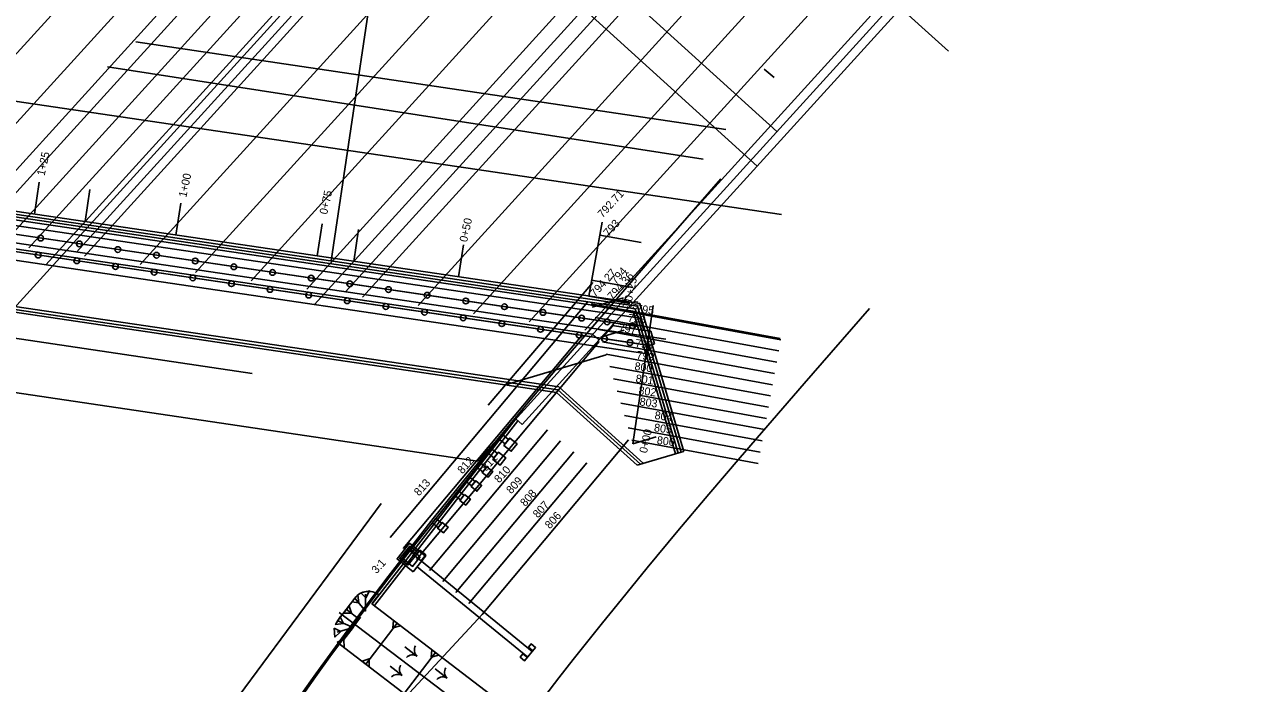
# Model space of a CAD drawing. Extents: x 1465887 to 1476191, y 569684 to 581027.
# Drawn here: x 1469836.1 to 1470052.7, y 573950.9 to 574066.2 of the extents above; entities that cross this region are included whole.
import ezdxf

# ---------------------------------------------------------------- set-up
doc = ezdxf.new("R2010")
doc.units = 0
for name, color, linetype in [('BR_P_Beam_Centerline', 7, 'Continuous'), ('BR_P_Brg_Centerline', 7, 'Continuous'), ('BR_P_Gen_Approach_Slab', 7, 'Continuous'), ('BR_P_Gen_Ground_Slope', 7, 'Continuous'), ('BR_P_Gen_Perforated_Pipe', 7, 'Continuous'), ('BR_P_Gen_Phase_Construction', 7, 'Continuous'), ('BR_P_Gen_Porous_Backfill', 7, 'Continuous'), ('BR_P_Gen_Profile_Grade', 7, 'Continuous'), ('BR_P_Gen_Slope_Protection', 7, 'Continuous'), ('BR_P_Rail_Object', 7, 'Continuous'), ('BR_P_Sub_Deep_Centerline', 7, 'Continuous'), ('BR_P_Sub_Deep_Hidden', 7, 'Continuous'), ('BR_P_Sub_Foot_Hidden', 7, 'Continuous'), ('BR_P_Sub_Hidden', 7, 'Continuous'), ('BR_P_Sub_Object', 7, 'Continuous'), ('BR_X_Sub_Hidden', 7, 'Continuous'), ('Default', 7, 'Continuous'), ('DR_P_Cells', 7, 'Continuous'), ('DR_P_Ditch', 7, 'Continuous'), ('DR_P_Erosion_Control', 7, 'Continuous'), ('DR_P_Headwall', 7, 'Continuous'), ('DR_P_Paved_Gutter', 7, 'Continuous'), ('DR_P_Storm_Sewer', 7, 'Continuous'), ('GK_Drainage_Nodes', 7, 'Continuous'), ('PV_X_Driveway', 7, 'Continuous'), ('PV_X_EOP', 7, 'Continuous'), ('PV_X_Shoulder', 7, 'Continuous'), ('RD_P_Anchor_Assembly', 7, 'Continuous'), ('SC_Scratch1', 7, 'Continuous'), ('SC_Scratch2', 7, 'Continuous')]:
    doc.layers.add(name, color=color, linetype=linetype)

msp = doc.modelspace()

# ---------------------------------------------------------------- linework, layer by layer
at = {"layer": 'BR_P_Beam_Centerline'}
for p, q in [((1469807.6, 574031.47), (1469918.67, 574153.77)), ((1469817.33, 574030.03), (1469928.4, 574152.33)), ((1469827.05, 574028.59), (1469938.12, 574150.89)), ((1469836.78, 574027.15), (1469947.84, 574149.45)), ((1469846.5, 574025.71), (1469957.57, 574148.01)), ((1469856.23, 574024.27), (1469967.29, 574146.57)), ((1469865.95, 574022.83), (1469977.02, 574145.13)), ((1469875.67, 574021.39), (1469986.74, 574143.69)), ((1469885.4, 574019.95), (1469996.47, 574142.25)), ((1469895.12, 574018.51), (1470006.19, 574140.81)), ((1469904.85, 574017.07), (1470015.91, 574139.37)), ((1469914.57, 574015.63), (1470025.64, 574137.93)), ((1469924.3, 574014.19), (1470035.36, 574136.49)), ((1469934.02, 574012.75), (1470045.09, 574135.05))]:
    msp.add_line(p, q, dxfattribs=at)
at = {"layer": 'BR_P_Brg_Centerline'}
msp.add_line((1469783.43, 574035.55), (1469948.19, 574011.16), dxfattribs=at)
at = {"layer": 'BR_P_Gen_Approach_Slab'}
for p, q in [((1469796.09, 574032.67), (1469935.4, 574012.04)), ((1469775.92, 574010.46), (1469915.23, 573989.83))]:
    msp.add_line(p, q, dxfattribs=at)
at = {"layer": 'BR_P_Gen_Ground_Slope'}
for p, q in [((1469934.72, 574018.72), (1469937.09, 574031.68)), ((1469936.67, 574029.4), (1469943.88, 574028.08)), ((1469935.23, 574021.53), (1469942.44, 574020.21)), ((1469934.72, 574018.72), (1469941.92, 574017.4)), ((1469934.51, 574017.67), (1469899.97, 573976.47)), ((1469935.13, 574017.34), (1469968.2, 574011.28)), ((1469935.18, 574017.15), (1469968.33, 574011.07)), ((1469935.82, 574014.99), (1469967.97, 574009.11)), ((1469936.46, 574012.84), (1469967.61, 574007.14)), ((1469933.52, 574011.82), (1469902.27, 573974.55)), ((1469936.56, 574010.77), (1469904.57, 573972.62)), ((1469937.1, 574010.69), (1469967.24, 574005.17)), ((1469937.75, 574008.54), (1469966.88, 574003.2)), ((1469938.39, 574006.39), (1469966.52, 574001.24)), ((1469939.03, 574004.24), (1469966.16, 573999.27)), ((1469939.67, 574002.09), (1469965.8, 573997.3)), ((1469940.31, 573999.94), (1469965.44, 573995.34)), ((1469940.95, 573997.79), (1469965.08, 573993.37)), ((1469927.49, 573995.29), (1469906.87, 573970.69)), ((1469941.59, 573995.64), (1469964.72, 573991.4)), ((1469929.79, 573993.36), (1469909.17, 573968.76)), ((1469941.69, 573993.54), (1469916.06, 573962.98)), ((1469942.23, 573993.49), (1469964.36, 573989.43)), ((1469932.09, 573991.43), (1469911.47, 573966.84)), ((1469934.39, 573989.5), (1469913.77, 573964.91)), ((1469916.06, 573962.98), (1469878.07, 573922.03))]:
    msp.add_line(p, q, dxfattribs=at)
at = {"layer": 'BR_P_Gen_Perforated_Pipe'}
for p, q in [((1469899.72, 574150.51), (1469997.64, 574061.59)), ((1469798.49, 574037.87), (1469942.86, 574016.5)), ((1469798.55, 574037.36), (1469942.47, 574016.05)), ((1469785.31, 574024.15), (1469929.51, 574002.81)), ((1469785.35, 574023.64), (1469929.29, 574002.33)), ((1469942.86, 574016.5), (1469950.38, 573991.23)), ((1469942.47, 574016.05), (1469949.9, 573991.09)), ((1469929.29, 574002.33), (1469943.76, 573989.26)), ((1469929.51, 574002.81), (1469944.32, 573989.43))]:
    msp.add_line(p, q, dxfattribs=at)
at = {"layer": 'BR_P_Gen_Phase_Construction'}
for p, q in [((1469839.72, 574024.19), (1469954.83, 574150.94)), ((1469845.12, 574026.42), (1469955.38, 574147.83)), ((1469886.75, 574017.22), (1470001.86, 574143.98)), ((1469892.16, 574019.46), (1469999.98, 574138.19))]:
    msp.add_line(p, q, dxfattribs=at)
at = {"layer": 'BR_P_Gen_Porous_Backfill'}
for p, q in [((1469785.4, 574023.13), (1469929.06, 574001.86)), ((1469929.06, 574001.86), (1469943.2, 573989.09)), ((1469943.2, 573989.09), (1469950.86, 573991.37))]:
    msp.add_line(p, q, dxfattribs=at)
at = {"layer": 'BR_P_Gen_Profile_Grade'}
msp.add_line((1465892.5, 569689.56), (1476184.47, 581022.69), dxfattribs=at)
at = {"layer": 'BR_P_Gen_Slope_Protection'}
for p, q in [((1469798.37, 574038.9), (1469943.64, 574017.39)), ((1469798.43, 574038.39), (1469942.04, 574017.13)), ((1469942.04, 574017.13), (1469943.25, 574016.95)), ((1469943.25, 574016.95), (1469950.86, 573991.37)), ((1469943.64, 574017.39), (1469951.34, 573991.52)), ((1469951.34, 573991.52), (1469950.86, 573991.37))]:
    msp.add_line(p, q, dxfattribs=at)
at = {"layer": 'BR_P_Rail_Object'}
for p, q in [((1469915.23, 573989.83), (1470067.44, 574157.44)), ((1469923.07, 573996.23), (1470068.55, 574156.43)), ((1469935.4, 574012.04), (1469936.51, 574011.03)), ((1469921.96, 573997.24), (1469923.07, 573996.23))]:
    msp.add_line(p, q, dxfattribs=at)
at = {"layer": 'BR_P_Sub_Deep_Centerline'}
for p, q in [((1469794.19, 574035.48), (1469943.45, 574013.38)), ((1469789.4, 574033.15), (1469943.18, 574010.39))]:
    msp.add_line(p, q, dxfattribs=at)
at = {"layer": 'BR_P_Sub_Deep_Hidden'}
for centre in [(1469838.84, 574028.87), (1469845.6, 574027.86), (1469852.36, 574026.86), (1469838.4, 574025.9), (1469845.16, 574024.9), (1469859.12, 574025.86), (1469865.88, 574024.86), (1469851.92, 574023.9), (1469858.68, 574022.9), (1469872.64, 574023.86), (1469879.4, 574022.86), (1469865.44, 574021.9), (1469872.2, 574020.89), (1469886.16, 574021.86), (1469892.92, 574020.86), (1469878.96, 574019.89), (1469885.72, 574018.89), (1469899.68, 574019.86), (1469906.44, 574018.86), (1469892.48, 574017.89), (1469899.24, 574016.89), (1469913.2, 574017.86), (1469919.96, 574016.86), (1469906, 574015.89), (1469912.76, 574014.89), (1469919.52, 574013.89), (1469926.72, 574015.86), (1469933.48, 574014.86), (1469937.93, 574014.2), (1469926.28, 574012.89), (1469933.04, 574011.89), (1469942.38, 574013.54), (1469937.49, 574011.23), (1469941.94, 574010.57)]:
    msp.add_circle(centre, 0.5, dxfattribs=at)
at = {"layer": 'BR_P_Sub_Foot_Hidden'}
for p, q in [((1469795.04, 574036.87), (1469943.7, 574014.86)), ((1469786.45, 574032.07), (1469944.6, 574008.66)), ((1469943.7, 574014.86), (1469944.33, 574012.74)), ((1469945.11, 574010.1), (1469945.3, 574009.47)), ((1469945.3, 574009.47), (1469944.6, 574008.66))]:
    msp.add_line(p, q, dxfattribs=at)
at = {"layer": 'BR_P_Sub_Hidden'}
for p, q in [((1469796.32, 574035.16), (1469939.21, 574014.01)), ((1469793.9, 574032.49), (1469936.78, 574011.33)), ((1469938.81, 574013.56), (1469939.21, 574014.01))]:
    msp.add_line(p, q, dxfattribs=at)
at = {"layer": 'BR_P_Sub_Object'}
for p, q in [((1469936.78, 574011.33), (1469938.81, 574013.56)), ((1469936.98, 574011.3), (1469939.01, 574013.53)), ((1469938.81, 574013.56), (1469944.51, 574012.72)), ((1469944.51, 574012.72), (1469945.6, 574012.56)), ((1469945.6, 574012.56), (1469946.25, 574010.36)), ((1469936.78, 574011.33), (1469945.3, 574010.07)), ((1469945.3, 574010.07), (1469946.25, 574010.36))]:
    msp.add_line(p, q, dxfattribs=at)
msp.add_lwpolyline([(1469936.78, 574011.33), (1469936.98, 574011.3), (1469939.01, 574013.53), (1469938.81, 574013.56)], close=True, dxfattribs=at)
at = {"layer": 'BR_X_Sub_Hidden'}
msp.add_line((1469968.46, 574033.03), (1469823.18, 574054.48), dxfattribs=at)
at = {"layer": 'Default'}
msp.add_lwpolyline([(1469867.09, 573922.18), (1469867.81, 573923.36), (1469870.08, 573927.01), (1469872.39, 573930.64), (1469874.73, 573934.25), (1469877.1, 573937.84), (1469879.51, 573941.42), (1469881.94, 573944.97), (1469884.41, 573948.51), (1469886.91, 573952.03), (1469889.43, 573955.53), (1469891.98, 573959.02), (1469894.55, 573962.49), (1469897.15, 573965.94), (1469899.77, 573969.38), (1469902.42, 573972.81), (1469903.75, 573974.52)], dxfattribs=at)
at = {"layer": 'DR_P_Cells'}
for points in [[(1469904, 573970.46), (1469906.19, 573973.19), (1469903.39, 573975.43), (1469901.2, 573972.7)], [(1469903.1, 573971.61), (1469904.88, 573973.82), (1469903.45, 573974.96), (1469901.67, 573972.75)], [(1469905.25, 573973.09), (1469903.9, 573971.4), (1469902.14, 573972.81), (1469903.5, 573974.49)]]:
    msp.add_lwpolyline(points, close=True, dxfattribs=at)
at = {"layer": 'DR_P_Ditch'}
msp.add_line((1469915.36, 573944.87), (1469891.08, 573963.33), dxfattribs=at)
at = {"layer": 'DR_P_Erosion_Control'}
for p, q in [((1469893.8, 573965.84), (1469890.76, 573961.87)), ((1469898.01, 573966.4), (1469896.8, 573964.82)), ((1469918.57, 573948.14), (1469896.8, 573964.82)), ((1469892.32, 573963.84), (1469894.64, 573962.08)), ((1469893.51, 573960.67), (1469891.89, 573958.58)), ((1469895.7, 573954.3), (1469901.18, 573961.45)), ((1469912.88, 573941.14), (1469891.32, 573957.67)), ((1469902.41, 573949.15), (1469907.89, 573956.3)), ((1469902.57, 573957.3), (1469904.67, 573955.69)), ((1469899.96, 573953.9), (1469902.06, 573952.28)), ((1469907.85, 573953.45), (1469909.95, 573951.84))]:
    msp.add_line(p, q, dxfattribs=at)
for points in [[(1469894.84, 573966.78), (1469896.37, 573967.09), (1469895.74, 573965.86)], [(1469893.25, 573965.21), (1469894.3, 573966.36), (1469894.52, 573965)], [(1469891.25, 573962.55), (1469890.44, 573961.21), (1469891.81, 573961.39)], [(1469892.79, 573964.41), (1469891.82, 573963.18), (1469893.2, 573963.19)], [(1469890.2, 573960.58), (1469890.32, 573959.02), (1469891.33, 573959.97)], [(1469900.57, 573961.94), (1469901.79, 573960.97), (1469900.45, 573960.66)], [(1469900.57, 573961.94), (1469901.79, 573960.97), (1469900.45, 573960.66)], [(1469890.69, 573958.13), (1469891.94, 573957.2), (1469891.89, 573958.58)], [(1469907.28, 573956.79), (1469908.51, 573955.82), (1469907.16, 573955.51)], [(1469907.28, 573956.79), (1469908.51, 573955.82), (1469907.16, 573955.51)], [(1469895.07, 573954.77), (1469896.33, 573953.83), (1469896.28, 573955.22)]]:
    msp.add_lwpolyline(points, close=True, dxfattribs=at)
for points in [[(1469893.79, 573965.84), (1469895.68, 573963.57), (1469895.67, 573966.51)], [(1469890.8, 573961.85), (1469893.51, 573960.67), (1469890.69, 573959.86)]]:
    msp.add_lwpolyline(points, dxfattribs=at)
for centre, radius, start, end in [((1469896.18, 573964.02), 3, 52.5361, 142.5361), ((1469903.91, 573954.39), 1.51, 59.558, 134.8196), ((1469905.73, 573956.76), 1.51, 150.2525, 225.5141), ((1469903.12, 573953.36), 1.51, 150.2525, 225.5141), ((1469911.01, 573952.91), 1.51, 150.2525, 225.5141), ((1469901.3, 573950.98), 1.51, 59.558, 134.8196), ((1469909.19, 573950.54), 1.51, 59.558, 134.8196)]:
    msp.add_arc(centre, radius, start, end, dxfattribs=at)
at = {"layer": 'DR_P_Headwall'}
msp.add_lwpolyline([(1469924.93, 573956.6), (1469924.16, 573957.23), (1469924.63, 573957.81), (1469925.41, 573957.18), (1469923.51, 573954.86), (1469922.73, 573955.49), (1469923.21, 573956.07), (1469923.98, 573955.44)], dxfattribs=at)
at = {"layer": 'DR_P_Paved_Gutter'}
for p, q in [((1469896.83, 573964.85), (1469921.96, 573997.24)), ((1469897.22, 573964.54), (1469922.33, 573996.9)), ((1469903.8, 573973.38), (1469904.2, 573973.08))]:
    msp.add_line(p, q, dxfattribs=at)
at = {"layer": 'DR_P_Storm_Sewer'}
for p, q in [((1469924.06, 573955.52), (1469904.7, 573971.34)), ((1469924.85, 573956.49), (1469905.49, 573972.31))]:
    msp.add_line(p, q, dxfattribs=at)
at = {"layer": 'GK_Drainage_Nodes'}
for p, q in [((1469902.3, 573974.07), (1469902.3, 573974.07)), ((1469902.82, 573973.65), (1469902.82, 573973.65)), ((1469904.37, 573973.79), (1469904.37, 573973.79)), ((1469903.02, 573972.1), (1469903.02, 573972.1)), ((1469903.7, 573972.95), (1469903.7, 573972.95)), ((1469903.7, 573972.95), (1469903.7, 573972.95)), ((1469903.7, 573972.95), (1469903.7, 573972.95)), ((1469903.99, 573972.71), (1469903.99, 573972.71)), ((1469903.99, 573972.71), (1469903.99, 573972.71)), ((1469904.57, 573972.24), (1469904.57, 573972.24)), ((1469905.09, 573971.82), (1469905.09, 573971.82)), ((1469923.68, 573956.65), (1469923.68, 573956.65)), ((1469924.46, 573956.02), (1469924.46, 573956.02)), ((1469924.46, 573956.02), (1469924.46, 573956.02)), ((1469924.46, 573956.02), (1469924.46, 573956.02)), ((1469924.46, 573956.02), (1469924.46, 573956.02)), ((1469924.46, 573956.02), (1469924.46, 573956.02))]:
    msp.add_line(p, q, dxfattribs=at)
at = {"layer": 'PV_X_Driveway'}
msp.add_lwpolyline([(1470490.67, 573700.83), (1470479.86, 573658.1), (1470459.64, 573614.53), (1470427.11, 573572.83), (1470388.22, 573539.31), (1470336.11, 573515.12), (1470281.02, 573499.93), (1470223.42, 573492.7), (1470166.22, 573493.96), (1470110.42, 573500.92), (1470053.31, 573516.43), (1469999.59, 573537.7), (1469946.66, 573567), (1469899.5, 573602.8), (1469858.29, 573648.66), (1469828.6, 573699.86), (1469815.03, 573750.54), (1469815.08, 573804.7), (1469829.85, 573864.39), (1469850.42, 573913.07), (1469873.55, 573948.79), (1469898.38, 573982.43)], dxfattribs=at)
at = {"layer": 'PV_X_EOP'}
msp.add_line((1469855.48, 574063.23), (1469958.72, 574047.87), dxfattribs=at)
at = {"layer": 'PV_X_Shoulder'}
msp.add_line((1469954.75, 574042.67), (1469850.53, 574058.83), dxfattribs=at)
at = {"layer": 'RD_P_Anchor_Assembly'}
for p, q in [((1469921.86, 573997.13), (1469903.75, 573974.52)), ((1469923.3, 573998.93), (1469903.77, 573974.53)), ((1469894.75, 573962.47), (1469892.47, 573959.37)), ((1469894.79, 573962.52), (1469892.5, 573959.42)), ((1469894.79, 573962.52), (1469892.5, 573959.42))]:
    msp.add_line(p, q, dxfattribs=at)
for points in [[(1469919.68, 573994.41), (1469919.07, 573993.64), (1469920.09, 573992.82), (1469920.71, 573993.59)], [(1469920.09, 573992.82), (1469920.71, 573993.59), (1469919.68, 573994.41), (1469919.07, 573993.64)], [(1469920.91, 573993.85), (1469919.89, 573992.57), (1469921.17, 573991.54), (1469922.19, 573992.82)], [(1469922.19, 573992.82), (1469921.17, 573991.54), (1469919.89, 573992.57), (1469920.91, 573993.85)], [(1469917.73, 573991.97), (1469917.12, 573991.21), (1469918.14, 573990.39), (1469918.75, 573991.15)], [(1469918.75, 573991.15), (1469918.14, 573990.39), (1469917.12, 573991.21), (1469917.73, 573991.97)], [(1469918.95, 573991.4), (1469917.93, 573990.12), (1469919.21, 573989.09), (1469920.23, 573990.37)], [(1469919.21, 573989.09), (1469920.23, 573990.37), (1469918.95, 573991.4), (1469917.93, 573990.12)], [(1469915.78, 573989.53), (1469915.16, 573988.77), (1469916.19, 573987.95), (1469916.8, 573988.71)], [(1469915.78, 573989.53), (1469915.16, 573988.77), (1469916.19, 573987.95), (1469916.8, 573988.71)], [(1469916.9, 573988.84), (1469916.08, 573987.82), (1469917.11, 573987), (1469917.93, 573988.02)], [(1469917.93, 573988.02), (1469917.11, 573987), (1469916.08, 573987.82), (1469916.9, 573988.84)], [(1469913.82, 573987.1), (1469913.21, 573986.33), (1469914.23, 573985.51), (1469914.85, 573986.28)], [(1469914.23, 573985.51), (1469914.85, 573986.28), (1469913.82, 573987.1), (1469913.21, 573986.33)], [(1469914.95, 573986.4), (1469914.13, 573985.38), (1469915.15, 573984.56), (1469915.97, 573985.58)], [(1469915.97, 573985.58), (1469915.15, 573984.56), (1469914.13, 573985.38), (1469914.95, 573986.4)], [(1469911.87, 573984.66), (1469911.25, 573983.89), (1469912.28, 573983.07), (1469912.89, 573983.84)], [(1469912.89, 573983.84), (1469912.28, 573983.07), (1469911.25, 573983.89), (1469911.87, 573984.66)], [(1469913, 573983.96), (1469912.18, 573982.94), (1469913.2, 573982.12), (1469914.02, 573983.14)], [(1469913, 573983.96), (1469912.18, 573982.94), (1469913.2, 573982.12), (1469914.02, 573983.14)], [(1469907.96, 573979.78), (1469907.35, 573979.01), (1469908.37, 573978.19), (1469908.99, 573978.96)], [(1469908.99, 573978.96), (1469908.37, 573978.19), (1469907.35, 573979.01), (1469907.96, 573979.78)], [(1469909.09, 573979.09), (1469908.27, 573978.06), (1469909.29, 573977.24), (1469910.11, 573978.27)], [(1469910.11, 573978.27), (1469909.29, 573977.24), (1469908.27, 573978.06), (1469909.09, 573979.09)], [(1469904.06, 573974.9), (1469903.44, 573974.13), (1469904.47, 573973.31), (1469905.08, 573974.08)], [(1469905.08, 573974.08), (1469904.47, 573973.31), (1469903.44, 573974.13), (1469904.06, 573974.9)], [(1469905.18, 573974.21), (1469904.36, 573973.18), (1469905.39, 573972.36), (1469906.21, 573973.39)], [(1469906.21, 573973.39), (1469905.39, 573972.36), (1469904.36, 573973.18), (1469905.18, 573974.21)]]:
    msp.add_lwpolyline(points, close=True, dxfattribs=at)
at = {"layer": 'SC_Scratch1'}
for p, q in [((1465887.32, 569694.27), (1476179.29, 581027.4)), ((1465899.17, 569683.51), (1476191.13, 581016.64)), ((1469889.68, 574024.88), (1469898.93, 574087.32)), ((1469965.43, 574058.45), (1469967.14, 574056.97)), ((1469838.6, 574038.67), (1469837.77, 574033.07)), ((1469847.42, 574037.36), (1469846.6, 574031.76)), ((1469863.33, 574035.01), (1469862.5, 574029.41)), ((1469888.06, 574031.35), (1469887.23, 574025.74)), ((1469894.46, 574030.4), (1469893.63, 574024.8)), ((1469912.79, 574027.69), (1469911.96, 574022.08)), ((1469935.42, 574021.11), (1469917.11, 573999.63)), ((1469940.78, 574018.43), (1469935.29, 574016.8)), ((1469942.42, 573992.84), (1469946, 574017.04)), ((1469828.79, 574012.16), (1469875.83, 574005.19)), ((1469940.94, 574012.75), (1469936.85, 574011.54)), ((1469920.14, 574003.18), (1469937.78, 574008.43)), ((1469946.51, 573994.05), (1469942.42, 573992.84))]:
    msp.add_line(p, q, dxfattribs=at)
for points in [[(1469884.54, 573949.12), (1469886.98, 573952.58), (1469889.46, 573956.02), (1469891.97, 573959.45), (1469894.5, 573962.86), (1469897.06, 573966.26), (1469899.64, 573969.65), (1469902.25, 573973.03), (1469904.88, 573976.4), (1469907.53, 573979.75), (1469910.2, 573983.1), (1469912.88, 573986.43), (1469918.32, 573993.09), (1469923.83, 573999.72), (1469929.39, 574006.32), (1469935, 574012.91), (1469940.66, 574019.49), (1469946.35, 574026.06), (1469957.82, 574039.23)], [(1469927.02, 573948.66), (1469929.5, 573951.88), (1469932.01, 573955.09), (1469934.55, 573958.31), (1469937.11, 573961.52), (1469939.67, 573964.69), (1469944.95, 573971.16), (1469950.29, 573977.59), (1469955.71, 573984.02), (1469961.21, 573990.48), (1469966.78, 573996.95), (1469972.4, 574003.44), (1469983.84, 574016.57)]]:
    msp.add_lwpolyline(points, dxfattribs=at)
at = {"layer": 'SC_Scratch2'}
for p, q in [((1469967.62, 574047.52), (1469836.22, 574166.85)), ((1469964.17, 574041.49), (1469875.33, 574122.16))]:
    msp.add_line(p, q, dxfattribs=at)

# ---------------------------------------------------------------- texts
at = {"layer": 'BR_P_Gen_Ground_Slope'}
for s, rotation, p in [('792.71', 47.7564, (1469937.15, 574032.31)), ('793', 47.7564, (1469938.16, 574029.04)), ('794.27', 47.7564, (1469935.83, 574018.46)), ('794.36', 47.7564, (1469938.86, 574017.91)), ('794', 47.7564, (1469939.43, 574020.69)), ('795', 352.3487, (1469940.24, 574016.78)), ('795', 352.3487, (1469942.97, 574015.88)), ('796', 352.3487, (1469941.47, 574014.23)), ('797', 352.3487, (1469939.87, 574012.47)), ('798', 352.3487, (1469942.79, 574009.82)), ('799', 352.3487, (1469943, 574007.76)), ('800', 352.3487, (1469942.66, 574005.79)), ('801', 352.3487, (1469942.87, 574003.63)), ('802', 352.3487, (1469943.35, 574001.54)), ('803', 352.3487, (1469943.55, 573999.59)), ('804', 352.3487, (1469946.18, 573997.2)), ('805', 352.3487, (1469946.08, 573995.04)), ('806', 352.3487, (1469946.57, 573992.84)), ('812', 47.7564, (1469912.63, 573987.49)), ('811', 47.7564, (1469916.79, 573987.96)), ('810', 47.7564, (1469919.06, 573985.9)), ('813', 47.7564, (1469905.02, 573983.62)), ('809', 47.7564, (1469921.16, 573983.99)), ('808', 47.7564, (1469923.6, 573981.78)), ('807', 47.7564, (1469925.82, 573979.76)), ('806', 47.7564, (1469927.92, 573977.86)), ('3:1', 47.7564, (1469897.6, 573970))]:
    msp.add_text(s, height=1.4, rotation=rotation, dxfattribs=at).set_placement(p)
at = {"layer": 'SC_Scratch1'}
for s, p in [('1+25', (1469839.52, 574039.7)), ('1+00', (1469864.31, 574035.92)), ('0+75', (1469888.95, 574032.93)), ('0+50', (1469913.44, 574028.09)), ('0+25', (1469942.28, 574017.7)), ('0+00', (1469944.9, 573991.13))]:
    msp.add_text(s, height=1.4, rotation=77.7564, dxfattribs=at).set_placement(p)

doc.saveas('drawing.dxf')
